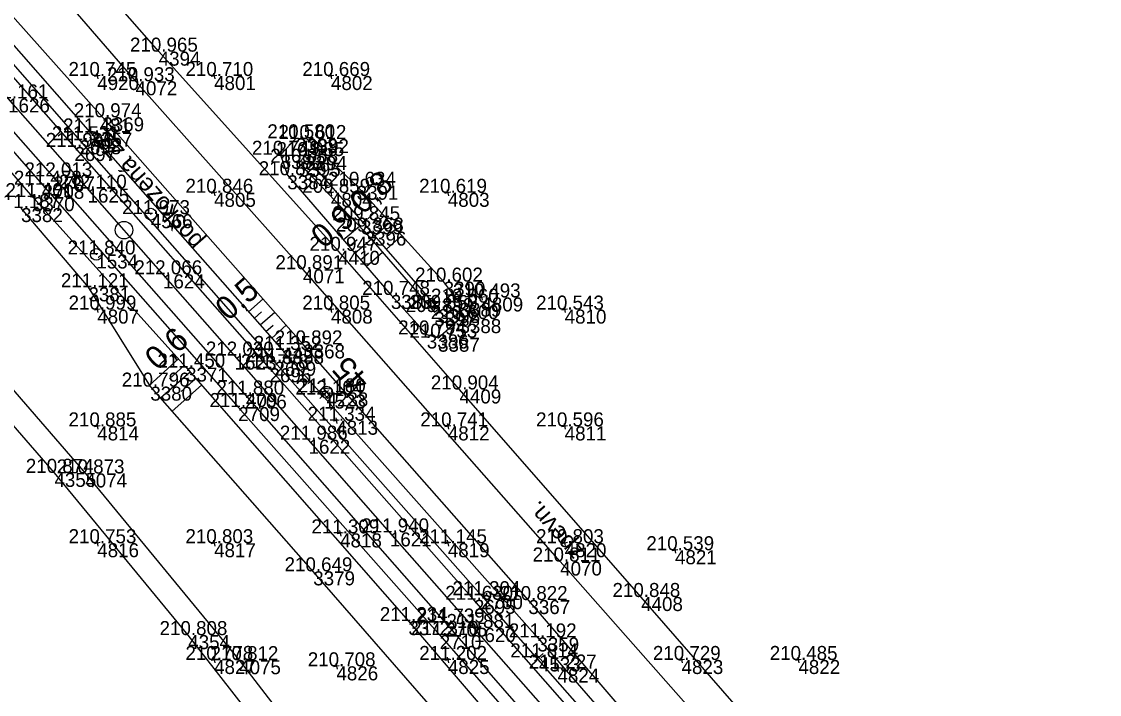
# Model space of a CAD drawing. Extents: x -556590 to -554855, y -1137918 to -1135717.
# Drawn here: x -555376.5 to -555284.2, y -1136813 to -1136755.3 of the extents above; entities that cross this region are included whole.
import ezdxf

# ---------------------------------------------------------------- set-up
doc = ezdxf.new("R2010")
doc.units = 0
for name, color, linetype in [('Vrstva 1', 7, 'Continuous'), ('Vrstva 11', 7, 'Continuous'), ('Vrstva 4', 7, 'Continuous'), ('Vrstva 48', 7, 'Continuous'), ('Vrstva 49', 7, 'Continuous'), ('Vrstva 50', 7, 'Continuous'), ('Vrstva 51', 7, 'Continuous'), ('Vrstva 60', 7, 'Continuous'), ('Vrstva 61', 7, 'Continuous'), ('Vrstva 7', 7, 'Continuous')]:
    doc.layers.add(name, color=color, linetype=linetype)

msp = doc.modelspace()

# ---------------------------------------------------------------- linework, layer by layer
at = {"layer": 'Vrstva 1'}
msp.add_lwpolyline([(-555292.626, -1136858.568), (-555299.342, -1136850.927), (-555304.528, -1136845.033), (-555310.842, -1136837.877), (-555317.094, -1136830.769), (-555323.668, -1136823.297), (-555330.793, -1136815.192), (-555337.757, -1136807.261), (-555344.959, -1136799.074), (-555351.92, -1136791.138), (-555358.253, -1136783.94), (-555364.373, -1136776.981), (-555370.831, -1136769.642), (-555377.628, -1136761.922), (-555384.655, -1136753.934), (-555391.964, -1136745.622), (-555398.234, -1136738.496), (-555405.21, -1136730.558), (-555412.028, -1136722.802), (-555418.861, -1136715.028), (-555425.943, -1136706.972)], dxfattribs=at)
at = {"layer": 'Vrstva 11'}
for p, q in [((-555350.708, -1136786.71), (-555350.044, -1136787.466)), ((-555349.96, -1136786.806), (-555350.663, -1136786.762)), ((-555349.886, -1136787.187), (-555350.313, -1136787.16))]:
    msp.add_line(p, q, dxfattribs=at)
msp.add_circle((-555350.376, -1136787.088), 0.503, dxfattribs=at)
msp.add_arc((-555350.376, -1136787.088), 0.503, 311.34221, 131.34221, dxfattribs=at)
at = {"layer": 'Vrstva 4'}
for points in [[(-555464.218, -1136660.059), (-555453.368, -1136672.228), (-555431.015, -1136697.892), (-555415.066, -1136715.862), (-555394.263, -1136739.423), (-555371.523, -1136765.495)], [(-555371.953, -1136766.077), (-555394.599, -1136740.194), (-555415.864, -1136716.157), (-555431.578, -1136698.204), (-555454.421, -1136672.369), (-555464.577, -1136660.557)], [(-555373.776, -1136768.598), (-555396.109, -1136743.261), (-555415.859, -1136720.785), (-555436.668, -1136697.089), (-555456.244, -1136674.795), (-555466.574, -1136663.075)], [(-555467.412, -1136663.795), (-555457.001, -1136675.466), (-555437.161, -1136698.083), (-555416.552, -1136721.586), (-555396.578, -1136744.252), (-555374.679, -1136769.31)], [(-555371.523, -1136765.495), (-555354.841, -1136784.465), (-555337.149, -1136804.45), (-555320.934, -1136822.853), (-555304.953, -1136840.644), (-555288.508, -1136859.289)], [(-555289.17, -1136860.014), (-555305.703, -1136840.862), (-555322.044, -1136822.792), (-555337.769, -1136804.848), (-555355.258, -1136785.023), (-555371.953, -1136766.077)], [(-555291.497, -1136862.482), (-555308.187, -1136843.573), (-555325.276, -1136823.876), (-555340.195, -1136806.793), (-555357.356, -1136787.276), (-555373.776, -1136768.598)], [(-555374.679, -1136769.31), (-555357.938, -1136788.343), (-555340.698, -1136807.868), (-555325.68, -1136825.055), (-555308.462, -1136844.804), (-555292.186, -1136863.185)]]:
    msp.add_lwpolyline(points, dxfattribs=at)
at = {"layer": 'Vrstva 48'}
for p, q in [((-555345.962, -1136771.424), (-555347.233, -1136772.576)), ((-555348.948, -1136774.033), (-555347.574, -1136772.845)), ((-555344.954, -1136772.535), (-555346.247, -1136773.707)), ((-555345.458, -1136771.98), (-555346.099, -1136772.561)), ((-555343.947, -1136773.647), (-555345.261, -1136774.838)), ((-555344.451, -1136773.091), (-555345.102, -1136773.682)), ((-555348.458, -1136774.6), (-555347.758, -1136773.996)), ((-555347.967, -1136775.168), (-555346.568, -1136773.958)), ((-555347.476, -1136775.735), (-555346.777, -1136775.13)), ((-555346.986, -1136776.302), (-555345.586, -1136775.092)), ((-555357.049, -1136780.183), (-555355.809, -1136779.09)), ((-555356.553, -1136780.745), (-555355.932, -1136780.199)), ((-555356.057, -1136781.308), (-555354.815, -1136780.214)), ((-555355.562, -1136781.871), (-555354.94, -1136781.323)), ((-555355.066, -1136782.434), (-555353.821, -1136781.338)), ((-555363.056, -1136784.228), (-555365.54, -1136786.46)), ((-555362.555, -1136784.786), (-555363.809, -1136785.913)), ((-555362.058, -1136785.348), (-555364.595, -1136787.571)), ((-555361.07, -1136786.476), (-555363.604, -1136788.697)), ((-555361.564, -1136785.912), (-555362.832, -1136787.023))]:
    msp.add_line(p, q, dxfattribs=at)
at = {"layer": 'Vrstva 49'}
for p, q in [((-555369.754, -1136759.953), (-555370.246, -1136760.047)), ((-555370.047, -1136759.754), (-555369.953, -1136760.246)), ((-555359.754, -1136759.953), (-555360.246, -1136760.047)), ((-555360.047, -1136759.754), (-555359.953, -1136760.246)), ((-555349.754, -1136759.953), (-555350.246, -1136760.047)), ((-555350.047, -1136759.754), (-555349.953, -1136760.246)), ((-555359.754, -1136769.953), (-555360.246, -1136770.047)), ((-555360.047, -1136769.754), (-555359.953, -1136770.246)), ((-555349.754, -1136769.953), (-555350.246, -1136770.047)), ((-555350.047, -1136769.754), (-555349.953, -1136770.246)), ((-555339.754, -1136769.953), (-555340.246, -1136770.047)), ((-555340.047, -1136769.754), (-555339.953, -1136770.246)), ((-555336.877, -1136778.912), (-555337.369, -1136779.006)), ((-555337.17, -1136778.713), (-555337.076, -1136779.205)), ((-555369.754, -1136779.953), (-555370.246, -1136780.047)), ((-555370.047, -1136779.754), (-555369.953, -1136780.246)), ((-555349.754, -1136779.953), (-555350.246, -1136780.047)), ((-555350.047, -1136779.754), (-555349.953, -1136780.246)), ((-555329.754, -1136779.953), (-555330.246, -1136780.047)), ((-555330.047, -1136779.754), (-555329.953, -1136780.246)), ((-555349.299, -1136789.468), (-555349.791, -1136789.562)), ((-555349.592, -1136789.269), (-555349.498, -1136789.761)), ((-555369.754, -1136789.953), (-555370.246, -1136790.047)), ((-555370.047, -1136789.754), (-555369.953, -1136790.246)), ((-555339.754, -1136789.953), (-555340.246, -1136790.047)), ((-555340.047, -1136789.754), (-555339.953, -1136790.246)), ((-555329.754, -1136789.953), (-555330.246, -1136790.047)), ((-555330.047, -1136789.754), (-555329.953, -1136790.246)), ((-555348.971, -1136799.113), (-555349.463, -1136799.207)), ((-555349.264, -1136798.914), (-555349.17, -1136799.406)), ((-555369.754, -1136799.953), (-555370.246, -1136800.047)), ((-555370.047, -1136799.754), (-555369.953, -1136800.246)), ((-555359.754, -1136799.953), (-555360.246, -1136800.047)), ((-555360.047, -1136799.754), (-555359.953, -1136800.246)), ((-555339.754, -1136799.953), (-555340.246, -1136800.047)), ((-555340.047, -1136799.754), (-555339.953, -1136800.246)), ((-555329.754, -1136799.953), (-555330.246, -1136800.047)), ((-555330.047, -1136799.754), (-555329.953, -1136800.246)), ((-555320.315, -1136800.555), (-555320.807, -1136800.649)), ((-555320.608, -1136800.356), (-555320.514, -1136800.848)), ((-555360.047, -1136809.754), (-555359.953, -1136810.246)), ((-555340.047, -1136809.754), (-555339.953, -1136810.246)), ((-555320.047, -1136809.754), (-555319.953, -1136810.246)), ((-555310.047, -1136809.754), (-555309.953, -1136810.246)), ((-555359.754, -1136809.953), (-555360.246, -1136810.047)), ((-555349.286, -1136810.496), (-555349.778, -1136810.59)), ((-555349.579, -1136810.297), (-555349.485, -1136810.789)), ((-555339.754, -1136809.953), (-555340.246, -1136810.047)), ((-555330.372, -1136810.683), (-555330.864, -1136810.777)), ((-555330.665, -1136810.484), (-555330.571, -1136810.976)), ((-555319.754, -1136809.953), (-555320.246, -1136810.047)), ((-555309.754, -1136809.953), (-555310.246, -1136810.047))]:
    msp.add_line(p, q, dxfattribs=at)
for points in [[(-555462.481, -1136658.477), (-555447.868, -1136674.77), (-555441.908, -1136681.306), (-555440.437, -1136682.042), (-555438.979, -1136683.028), (-555437.999, -1136684.209), (-555437.207, -1136685.699), (-555436.367, -1136687.463), (-555429.629, -1136694.949), (-555415.083, -1136712.3), (-555396.41, -1136733.354), (-555369.563, -1136763.534)], [(-555370.568, -1136764.836), (-555388.121, -1136744.839), (-555403.174, -1136727.841), (-555422.805, -1136705.916), (-555438.448, -1136687.784), (-555439.221, -1136685.925), (-555439.336, -1136684.967), (-555440.313, -1136683.852), (-555441.662, -1136683.489), (-555443.41, -1136682.015), (-555453.962, -1136670.239), (-555463.79, -1136659.785)], [(-555375.504, -1136770.371), (-555385.698, -1136758.59), (-555398.865, -1136742.932), (-555418.134, -1136721.358), (-555433.023, -1136704.484), (-555449.478, -1136685.627), (-555458.298, -1136675.411), (-555468.03, -1136664.433)], [(-555267.42, -1136881.24), (-555276.299, -1136870.493), (-555297.11, -1136845.788), (-555314.807, -1136826.184), (-555333.105, -1136804.868), (-555352.371, -1136782.978), (-555369.563, -1136763.534)], [(-555370.568, -1136764.836), (-555354.167, -1136783.454), (-555332.335, -1136808.07), (-555314.049, -1136829.129), (-555294.571, -1136850.932), (-555277.261, -1136871.194), (-555267.42, -1136881.24)], [(-555354.308, -1136766.744), (-555353.734, -1136768.499), (-555344.875, -1136778.743), (-555341.802, -1136782.13), (-555340.836, -1136782.407), (-555339.003, -1136780.814), (-555338.995, -1136779.407), (-555340.358, -1136777.606), (-555347.801, -1136769.395), (-555352.038, -1136765.397), (-555352.997, -1136765.336), (-555354.308, -1136766.744)], [(-555352.209, -1136766.856), (-555352.742, -1136767.423), (-555347.121, -1136773.32), (-555341.153, -1136780.209), (-555340.808, -1136779.945), (-555347.43, -1136772.35), (-555352.209, -1136766.856)], [(-555375.504, -1136770.371), (-555362.401, -1136784.957), (-555343.37, -1136806.672), (-555328.229, -1136824.382), (-555317.146, -1136837.289), (-555302.963, -1136853.472), (-555293.054, -1136864.302)], [(-555294.757, -1136865.971), (-555305.219, -1136854.428), (-555319.01, -1136839.008), (-555333.931, -1136822.633), (-555351.517, -1136802.409), (-555365.456, -1136786.595), (-555370.754, -1136778.091), (-555376.519, -1136771.305)]]:
    msp.add_lwpolyline(points, dxfattribs=at)
at = {"layer": 'Vrstva 50'}
msp.add_line((-555365.384, -1136771.866), (-555365.45, -1136771.79), dxfattribs=at)
msp.add_circle((-555365.417, -1136771.828), 0.5, dxfattribs=at)
at = {"layer": 'Vrstva 51'}
for points in [[(-555404.363, -1136697.548), (-555406.381, -1136701.136), (-555407.048, -1136702.906), (-555407.526, -1136704.889), (-555407.633, -1136706.974), (-555407.416, -1136708.768), (-555406.759, -1136712.144), (-555405.956, -1136714.438), (-555404.741, -1136716.632), (-555402.685, -1136719.394), (-555395.161, -1136727.928), (-555381.917, -1136742.903), (-555366.721, -1136760.451)], [(-555364.742, -1136757.914), (-555379.018, -1136741.623), (-555394.75, -1136723.416), (-555400.881, -1136716.109), (-555402.646, -1136713.261), (-555403.709, -1136710.443), (-555404.167, -1136707.921), (-555404.024, -1136705.061), (-555403.449, -1136703.098), (-555402.147, -1136700.124)], [(-555279.712, -1136854.445), (-555288.387, -1136844.922), (-555298.101, -1136833.391), (-555304.289, -1136826.181), (-555310.443, -1136819.539), (-555323.457, -1136804.607), (-555339.001, -1136786.837), (-555349.383, -1136774.966), (-555364.742, -1136757.914)], [(-555282.189, -1136856.867), (-555295.864, -1136840.948), (-555312.722, -1136821.571), (-555330.387, -1136801.569), (-555352.399, -1136776.543), (-555366.721, -1136760.451)], [(-555383.133, -1136780.034), (-555371.019, -1136794.027), (-555357.856, -1136810.017), (-555348.873, -1136821.694), (-555344.974, -1136826.436), (-555334.907, -1136838.358), (-555326.693, -1136847.522), (-555317.198, -1136857.303), (-555297.774, -1136877.911)], [(-555299.492, -1136878.918), (-555314.22, -1136863.297), (-555324.704, -1136852.499), (-555328.854, -1136848.099), (-555333.693, -1136842.852), (-555339.538, -1136836.114), (-555346.724, -1136827.487), (-555354.139, -1136818.234), (-555362.213, -1136807.869), (-555373.662, -1136793.978), (-555384.667, -1136781.315)]]:
    msp.add_lwpolyline(points, dxfattribs=at)
at = {"layer": 'Vrstva 60'}
for p, q in [((-555364.742, -1136757.914), (-555364.742, -1136757.914)), ((-555370, -1136760), (-555370, -1136760)), ((-555366.721, -1136760.451), (-555366.721, -1136760.451)), ((-555360, -1136760), (-555360, -1136760)), ((-555350, -1136760), (-555350, -1136760)), ((-555369.563, -1136763.534), (-555369.563, -1136763.534)), ((-555371.523, -1136765.495), (-555371.523, -1136765.495)), ((-555370.568, -1136764.836), (-555370.568, -1136764.836)), ((-555352.997, -1136765.336), (-555352.997, -1136765.336)), ((-555352.038, -1136765.397), (-555352.038, -1136765.397)), ((-555371.953, -1136766.077), (-555371.953, -1136766.077)), ((-555354.308, -1136766.744), (-555354.308, -1136766.744)), ((-555352.209, -1136766.856), (-555352.209, -1136766.856)), ((-555352.742, -1136767.423), (-555352.742, -1136767.423)), ((-555373.776, -1136768.598), (-555373.776, -1136768.598)), ((-555353.734, -1136768.499), (-555353.734, -1136768.499)), ((-555374.679, -1136769.31), (-555374.679, -1136769.31)), ((-555370.831, -1136769.642), (-555370.831, -1136769.642)), ((-555360, -1136770), (-555360, -1136770)), ((-555350, -1136770), (-555350, -1136770)), ((-555347.801, -1136769.395), (-555347.801, -1136769.395)), ((-555340, -1136770), (-555340, -1136770)), ((-555375.504, -1136770.371), (-555375.504, -1136770.371)), ((-555365.417, -1136771.828), (-555365.417, -1136771.828)), ((-555347.43, -1136772.35), (-555347.43, -1136772.35)), ((-555347.121, -1136773.32), (-555347.121, -1136773.32)), ((-555370.08, -1136775.28), (-555370.08, -1136775.28)), ((-555349.383, -1136774.966), (-555349.383, -1136774.966)), ((-555352.399, -1136776.543), (-555352.399, -1136776.543)), ((-555364.373, -1136776.981), (-555364.373, -1136776.981)), ((-555370.754, -1136778.091), (-555370.754, -1136778.091)), ((-555340.358, -1136777.606), (-555340.358, -1136777.606)), ((-555344.875, -1136778.743), (-555344.875, -1136778.743)), ((-555337.123, -1136778.959), (-555337.123, -1136778.959)), ((-555370, -1136780), (-555370, -1136780)), ((-555350, -1136780), (-555350, -1136780)), ((-555341.153, -1136780.209), (-555341.153, -1136780.209)), ((-555340.808, -1136779.945), (-555340.808, -1136779.945)), ((-555338.995, -1136779.407), (-555338.995, -1136779.407)), ((-555330, -1136780), (-555330, -1136780)), ((-555339.003, -1136780.814), (-555339.003, -1136780.814)), ((-555352.371, -1136782.978), (-555352.371, -1136782.978)), ((-555341.802, -1136782.13), (-555341.802, -1136782.13)), ((-555340.836, -1136782.407), (-555340.836, -1136782.407)), ((-555358.253, -1136783.94), (-555358.253, -1136783.94)), ((-555354.167, -1136783.454), (-555354.167, -1136783.454)), ((-555354.841, -1136784.465), (-555354.841, -1136784.465)), ((-555362.401, -1136784.957), (-555362.401, -1136784.957)), ((-555355.258, -1136785.023), (-555355.258, -1136785.023)), ((-555365.456, -1136786.595), (-555365.456, -1136786.595)), ((-555357.356, -1136787.276), (-555357.356, -1136787.276)), ((-555350.585, -1136787.269), (-555350.585, -1136787.269)), ((-555350.376, -1136787.088), (-555350.376, -1136787.088)), ((-555339.001, -1136786.837), (-555339.001, -1136786.837)), ((-555357.938, -1136788.343), (-555357.938, -1136788.343)), ((-555370, -1136790), (-555370, -1136790)), ((-555349.545, -1136789.515), (-555349.545, -1136789.515)), ((-555340, -1136790), (-555340, -1136790)), ((-555330, -1136790), (-555330, -1136790)), ((-555351.92, -1136791.138), (-555351.92, -1136791.138)), ((-555373.662, -1136793.978), (-555373.662, -1136793.978)), ((-555371.019, -1136794.027), (-555371.019, -1136794.027)), ((-555349.217, -1136799.16), (-555349.217, -1136799.16)), ((-555344.959, -1136799.074), (-555344.959, -1136799.074)), ((-555370, -1136800), (-555370, -1136800)), ((-555360, -1136800), (-555360, -1136800)), ((-555340, -1136800), (-555340, -1136800)), ((-555330, -1136800), (-555330, -1136800)), ((-555320.561, -1136800.602), (-555320.561, -1136800.602)), ((-555330.387, -1136801.569), (-555330.387, -1136801.569)), ((-555351.517, -1136802.409), (-555351.517, -1136802.409)), ((-555337.769, -1136804.848), (-555337.769, -1136804.848)), ((-555337.149, -1136804.45), (-555337.149, -1136804.45)), ((-555333.105, -1136804.868), (-555333.105, -1136804.868)), ((-555323.457, -1136804.607), (-555323.457, -1136804.607)), ((-555343.37, -1136806.672), (-555343.37, -1136806.672)), ((-555340.195, -1136806.793), (-555340.195, -1136806.793)), ((-555362.213, -1136807.869), (-555362.213, -1136807.869)), ((-555340.698, -1136807.868), (-555340.698, -1136807.868)), ((-555337.757, -1136807.261), (-555337.757, -1136807.261)), ((-555332.335, -1136808.07), (-555332.335, -1136808.07)), ((-555332.206, -1136809.779), (-555332.206, -1136809.779)), ((-555360, -1136810), (-555360, -1136810)), ((-555357.856, -1136810.017), (-555357.856, -1136810.017)), ((-555349.532, -1136810.543), (-555349.532, -1136810.543)), ((-555340, -1136810), (-555340, -1136810)), ((-555320, -1136810), (-555320, -1136810)), ((-555310, -1136810), (-555310, -1136810)), ((-555330.618, -1136810.73), (-555330.618, -1136810.73))]:
    msp.add_line(p, q, dxfattribs=at)
at = {"layer": 'Vrstva 7'}
for p, q in [((-555370.03, -1136775.28), (-555370.13, -1136775.28)), ((-555350.21, -1136786.939), (-555350.96, -1136787.599)), ((-555350.915, -1136786.894), (-555350.255, -1136787.644)), ((-555332.582, -1136810.109), (-555331.83, -1136809.449)), ((-555331.876, -1136810.155), (-555332.536, -1136809.403))]:
    msp.add_line(p, q, dxfattribs=at)
for centre, radius in [((-555367.707, -1136773.192), 0.75), ((-555370.08, -1136775.28), 0.5)]:
    msp.add_circle(centre, radius, dxfattribs=at)

# ---------------------------------------------------------------- texts
at = {"layer": 'Vrstva 11'}
msp.add_text('45', height=2, rotation=131.34221, dxfattribs=at).set_placement((-555346.582, -1136786.058))
at = {"layer": 'Vrstva 48'}
for s, rotation, p in [('0,8', 42.19127, (-555347.286, -1136771.934)), ('0,9', 40.85321, (-555350.623, -1136774.853)), ('0,5', 41.37753, (-555358.796, -1136781.042)), ('0,6', 41.93421, (-555364.803, -1136785.316))]:
    msp.add_text(s, height=2, rotation=rotation, dxfattribs=at).set_placement(p)
at = {"layer": 'Vrstva 50'}
msp.add_text('poškozená ZZ', height=1.5, rotation=131.34637, dxfattribs=at).set_placement((-555360.809, -1136774.072))
at = {"layer": 'Vrstva 51'}
msp.add_text('zpevn.', height=1.5, rotation=131.17725, dxfattribs=at).set_placement((-555328.327, -1136800.682))
at = {"layer": 'Vrstva 60'}
for s, p in [('4394', (-555364.742, -1136759.114)), ('4920', (-555370, -1136761.2)), ('4072', (-555366.721, -1136761.651)), ('4801', (-555360, -1136761.2)), ('4802', (-555350, -1136761.2)), ('1626', (-555377.628, -1136763.122)), ('3369', (-555369.563, -1136764.734)), ('2698', (-555371.523, -1136766.695)), ('3357', (-555370.568, -1136766.036)), ('3393', (-555352.997, -1136766.536)), ('3392', (-555352.038, -1136766.597)), ('2697', (-555371.953, -1136767.277)), ('3383', (-555354.308, -1136767.944)), ('3394', (-555352.209, -1136768.056)), ('3395', (-555352.742, -1136768.623)), ('2707', (-555373.776, -1136769.798)), ('3384', (-555353.734, -1136769.699)), ('2708', (-555374.679, -1136770.51)), ('1625', (-555370.831, -1136770.842)), ('4805', (-555360, -1136771.2)), ('4804', (-555350, -1136771.2)), ('3391', (-555347.801, -1136770.595)), ('4803', (-555340, -1136771.2)), ('3370', (-555375.504, -1136771.571)), ('3382', (-555376.519, -1136772.505)), ('4566', (-555365.417, -1136773.028)), ('3399', (-555347.43, -1136773.55)), ('3396', (-555347.121, -1136774.52)), ('1534', (-555370.08, -1136776.48)), ('4410', (-555349.383, -1136776.166)), ('4071', (-555352.399, -1136777.743)), ('1624', (-555364.373, -1136778.181)), ('3381', (-555370.754, -1136779.291)), ('3390', (-555340.358, -1136778.806)), ('3385', (-555344.875, -1136779.943)), ('4809', (-555337.123, -1136780.159)), ('4807', (-555370, -1136781.2)), ('4808', (-555350, -1136781.2)), ('3397', (-555341.153, -1136781.409)), ('3398', (-555340.808, -1136781.145)), ('3389', (-555338.995, -1136780.607)), ('4810', (-555330, -1136781.2)), ('3388', (-555339.003, -1136782.014)), ('3368', (-555352.371, -1136784.178)), ('3386', (-555341.802, -1136783.33)), ('3387', (-555340.836, -1136783.607)), ('1623', (-555358.253, -1136785.14)), ('3358', (-555354.167, -1136784.654)), ('2699', (-555354.841, -1136785.665)), ('3371', (-555362.401, -1136786.157)), ('2696', (-555355.258, -1136786.223)), ('3380', (-555365.456, -1136787.795)), ('2706', (-555357.356, -1136788.476)), ('1523', (-555350.585, -1136788.469)), ('4238', (-555350.376, -1136788.288)), ('4409', (-555339.001, -1136788.037)), ('2709', (-555357.938, -1136789.543)), ('4814', (-555370, -1136791.2)), ('4813', (-555349.545, -1136790.715)), ('4812', (-555340, -1136791.2)), ('4811', (-555330, -1136791.2)), ('1622', (-555351.92, -1136792.338)), ('4355', (-555373.662, -1136795.178)), ('4074', (-555371.019, -1136795.227)), ('4818', (-555349.217, -1136800.36)), ('1621', (-555344.959, -1136800.274)), ('4816', (-555370, -1136801.2)), ('4817', (-555360, -1136801.2)), ('4819', (-555340, -1136801.2)), ('4820', (-555330, -1136801.2)), ('4821', (-555320.561, -1136801.802)), ('3379', (-555351.517, -1136803.609)), ('4070', (-555330.387, -1136802.769)), ('2695', (-555337.769, -1136806.048)), ('2700', (-555337.149, -1136805.65)), ('3367', (-555333.105, -1136806.068)), ('4408', (-555323.457, -1136805.807)), ('3372', (-555343.37, -1136807.872)), ('2705', (-555340.195, -1136807.993)), ('4354', (-555362.213, -1136809.069)), ('2710', (-555340.698, -1136809.068)), ('1620', (-555337.757, -1136808.461)), ('3359', (-555332.335, -1136809.27)), ('4533', (-555332.206, -1136810.979)), ('4827', (-555360, -1136811.2)), ('4075', (-555357.856, -1136811.217)), ('4826', (-555349.532, -1136811.743)), ('4825', (-555340, -1136811.2)), ('4823', (-555320, -1136811.2)), ('4822', (-555310, -1136811.2)), ('4824', (-555330.618, -1136811.93))]:
    msp.add_text(s, height=1.2, dxfattribs=at).set_placement(p)
at = {"layer": 'Vrstva 61'}
for s, p in [('210.965', (-555367.198, -1136757.914)), ('210.745', (-555372.456, -1136760)), ('210.710', (-555362.451, -1136760)), ('210.669', (-555352.454, -1136760)), ('210.933', (-555369.173, -1136760.451)), ('212.161', (-555379.985, -1136761.922)), ('210.974', (-555372.014, -1136763.534)), ('211.481', (-555372.925, -1136764.836)), ('211.531', (-555373.88, -1136765.495)), ('210.580', (-555355.448, -1136765.336)), ('210.612', (-555354.486, -1136765.397)), ('211.906', (-555374.405, -1136766.077)), ('210.749', (-555356.762, -1136766.744)), ('210.058', (-555355.196, -1136767.423)), ('210.035', (-555354.665, -1136766.856)), ('210.826', (-555356.186, -1136768.499)), ('211.478', (-555377.133, -1136769.31)), ('212.013', (-555376.228, -1136768.598)), ('210.634', (-555350.252, -1136769.395)), ('211.401', (-555377.861, -1136770.371)), ('212.110', (-555373.282, -1136769.642)), ('210.846', (-555362.452, -1136770)), ('209.859', (-555352.454, -1136770)), ('210.619', (-555342.454, -1136770)), ('211.187', (-555378.971, -1136771.305)), ('211.973', (-555367.869, -1136771.828)), ('209.845', (-555349.886, -1136772.35)), ('209.868', (-555349.575, -1136773.32)), ('210.947', (-555351.835, -1136774.966)), ('211.840', (-555372.531, -1136775.28)), ('210.891', (-555354.756, -1136776.543)), ('212.066', (-555366.825, -1136776.981)), ('210.602', (-555342.806, -1136777.606)), ('211.121', (-555373.111, -1136778.091)), ('210.748', (-555347.329, -1136778.743)), ('210.560', (-555341.446, -1136779.407)), ('210.493', (-555339.575, -1136778.959)), ('210.999', (-555372.454, -1136780)), ('210.805', (-555352.456, -1136780)), ('209.899', (-555343.607, -1136780.209)), ('209.850', (-555343.259, -1136779.945)), ('210.543', (-555332.452, -1136780)), ('210.600', (-555341.454, -1136780.814)), ('210.794', (-555344.253, -1136782.13)), ('210.892', (-555354.819, -1136782.978)), ('210.753', (-555343.288, -1136782.407)), ('212.030', (-555360.704, -1136783.94)), ('211.352', (-555356.615, -1136783.454)), ('211.450', (-555364.852, -1136784.957)), ('211.778', (-555357.712, -1136785.023)), ('211.442', (-555357.289, -1136784.465)), ('210.796', (-555367.908, -1136786.595)), ('210.904', (-555341.452, -1136786.837)), ('211.880', (-555359.807, -1136787.276)), ('212.104', (-555353.036, -1136787.269)), ('211.180', (-555352.827, -1136787.088)), ('211.409', (-555360.392, -1136788.343)), ('211.334', (-555351.996, -1136789.515)), ('210.885', (-555372.456, -1136790)), ('210.741', (-555342.357, -1136790)), ('210.596', (-555332.452, -1136790)), ('211.986', (-555354.372, -1136791.138)), ('210.874', (-555376.113, -1136793.978)), ('210.873', (-555373.471, -1136794.027)), ('211.309', (-555351.671, -1136799.16)), ('211.940', (-555347.41, -1136799.074)), ('210.753', (-555372.452, -1136800)), ('210.803', (-555362.452, -1136800)), ('211.145', (-555342.456, -1136800)), ('210.803', (-555332.452, -1136800)), ('210.539', (-555323.015, -1136800.602)), ('210.811', (-555332.744, -1136801.569)), ('210.649', (-555353.971, -1136802.409)), ('211.304', (-555339.6, -1136804.45)), ('211.630', (-555340.22, -1136804.848)), ('210.822', (-555335.553, -1136804.868)), ('210.848', (-555325.911, -1136804.607)), ('211.234', (-555345.821, -1136806.672)), ('211.739', (-555342.649, -1136806.793)), ('211.881', (-555340.114, -1136807.261)), ('210.808', (-555364.667, -1136807.869)), ('211.310', (-555343.149, -1136807.868)), ('211.192', (-555334.783, -1136808.07)), ('210.778', (-555362.454, -1136810)), ('210.812', (-555360.304, -1136810.017)), ('211.202', (-555342.448, -1136810)), ('211.814', (-555334.657, -1136809.779)), ('210.729', (-555322.454, -1136810)), ('210.485', (-555312.456, -1136810)), ('210.708', (-555351.986, -1136810.543)), ('211.227', (-555333.07, -1136810.73))]:
    msp.add_text(s, height=1.2, dxfattribs=at).set_placement(p)

doc.saveas('drawing.dxf')
